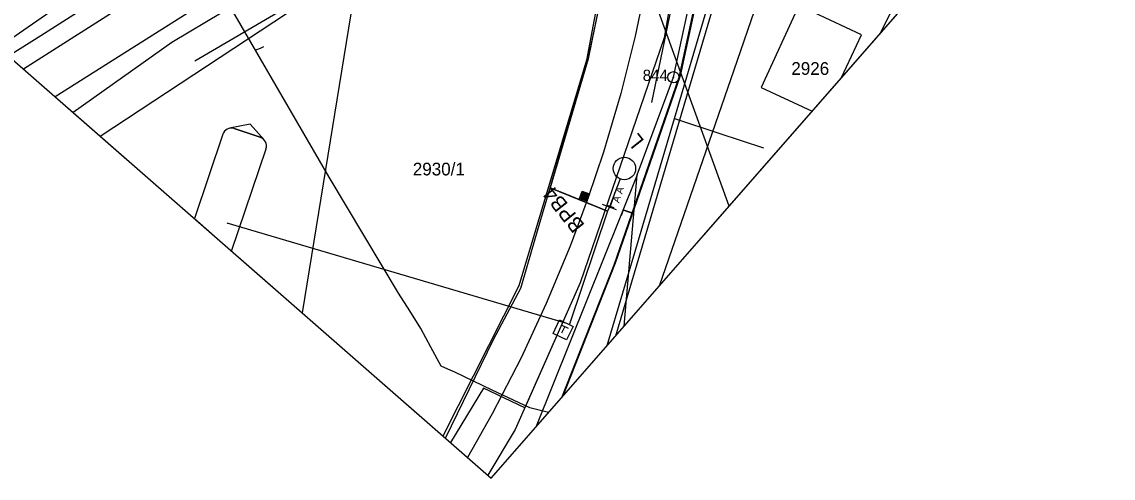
# Model space of a CAD drawing. Extents: x -620475 to -619963, y -1123010 to -1122510.
# Drawn here: x -620221.2 to -620075.4, y -1123010.1 to -1122949.2 of the extents above; entities that cross this region are included whole.
import ezdxf

# ---------------------------------------------------------------- set-up
doc = ezdxf.new("R2010")
doc.units = 0
for name, color, linetype in [('CETIN', 7, 'Continuous'), ('HranDP', 7, 'Continuous'), ('Hranice parcel', 7, 'Continuous'), ('Level 10', 7, 'Continuous'), ('lomové body trasa', 7, 'Continuous'), ('Parcelní čísla', 7, 'Continuous'), ('PS 06-14-01_trasa_sdělovací_nové', 7, 'Continuous'), ('PS6-14-01_bubliny', 7, 'Continuous'), ('Rámečky', 7, 'Continuous'), ('Rámečky-tisk', 7, 'Continuous'), ('SSZT', 7, 'Continuous'), ('SSZT-DK', 7, 'Continuous'), ('SSZT-OSS', 7, 'Continuous'), ('SSZT-TK', 7, 'Continuous'), ('VAS el kabel', 7, 'Continuous'), ('VAS vodovod', 7, 'Continuous'), ('Vnitřní kresba', 7, 'Continuous'), ('Vrstva 1', 7, 'Continuous'), ('Vrstva 2', 7, 'Continuous'), ('Vrstva 3', 7, 'Continuous'), ('Vrstva 6', 7, 'Continuous'), ('Značky bodu BP', 7, 'Continuous'), ('ČD-T', 7, 'Continuous'), ('ČD-T OSS Ždár', 7, 'Continuous')]:
    doc.layers.add(name, color=color, linetype=linetype)

# ---------------------------------------------------------------- blocks, each defined once
blk = doc.blocks.new('C535')
at = {"layer": 'Level 10'}
for p, q in [((-0.5, 0.5), (0.5, 0.5)), ((0, 0.5), (0, -0.5))]:
    blk.add_line(p, q, dxfattribs=at)
blk.add_lwpolyline([(-1, 1), (1, 1), (1, -1), (-1, -1), (-1, 1)], dxfattribs=at)

msp = doc.modelspace()

# ---------------------------------------------------------------- linework, layer by layer
at = {"layer": 'CETIN'}
for points in [[(-620222.97, -1122953.74), (-620218.63, -1122950.99), (-620187.55, -1122931.18), (-620162.84, -1122907.83)], [(-620210.74, -1122964.44), (-620141.26, -1122918.68), (-620127.25, -1122919.48)], [(-620084.31, -1122923.86), (-620095.91, -1122929.69), (-620106.59, -1122950.81)]]:
    msp.add_lwpolyline(points, dxfattribs=at)
at = {"layer": 'HranDP'}
for points in [[(-620139.01, -1122969.61), (-620134.15, -1122956.58), (-620131.17, -1122942.74), (-620127.22, -1122908.12)], [(-620139.31, -1122915.18), (-620140.08, -1122924.01), (-620145.74, -1122954.29), (-620154.8, -1122984.44), (-620164.93, -1123004.51)], [(-620139.01, -1122969.61), (-620152.54, -1123003.33)]]:
    msp.add_lwpolyline(points, dxfattribs=at)
at = {"layer": 'Hranice parcel'}
for p, q in [((-620224.32, -1122952.56), (-620208, -1122941.31)), ((-620201.16, -1122951.94), (-620214.32, -1122961.31)), ((-620140.71, -1122989.82), (-620139.01, -1122969.61))]:
    msp.add_line(p, q, dxfattribs=at)
for points in [[(-620139.01, -1122969.61), (-620134.15, -1122956.58), (-620131.17, -1122942.74), (-620127.22, -1122908.12)], [(-620139.31, -1122915.18), (-620140.08, -1122924.01), (-620145.74, -1122954.29), (-620154.8, -1122984.44), (-620164.93, -1123004.51)], [(-620175.35, -1122936.6), (-620194.44, -1122947.94), (-620201.16, -1122951.94)], [(-620175.35, -1122936.6), (-620183.73, -1122988.07)], [(-620111.68, -1122956.63), (-620109.02, -1122950.94), (-620117.41, -1122947.01), (-620122.42, -1122957.94)], [(-620122.42, -1122957.94), (-620115.6, -1122961.11)], [(-620139.01, -1122969.61), (-620152.54, -1123003.33)]]:
    msp.add_lwpolyline(points, dxfattribs=at)
at = {"layer": 'lomové body trasa'}
msp.add_line((-620142.94, -1122974.46), (-620148.04, -1122989.57), dxfattribs=at)
at = {"layer": 'PS 06-14-01_trasa_sdělovací_nové'}
for points in [[(-620158.91, -1122820.61), (-620151.64, -1122838.53), (-620148.85, -1122845.74), (-620147.08, -1122852.39), (-620142.65, -1122873.56), (-620132.31, -1122871.72), (-620130.54, -1122883.68), (-620129.88, -1122892.6), (-620129.3, -1122896.72), (-620128.92, -1122908.69), (-620129.36, -1122914.83), (-620129.69, -1122921.33), (-620138.78, -1122920.93), (-620145.54, -1122954.13), (-620150.63, -1122971.37), (-620142.94, -1122974.46), (-620142.94, -1122974.46)], [(-620164.58, -1123004.82), (-620158.18, -1122991.64), (-620154.53, -1122984.74), (-620154, -1122982.93), (-620152.3, -1122977.09), (-620150.63, -1122971.37)]]:
    msp.add_lwpolyline(points, dxfattribs=at)
at = {"layer": 'PS6-14-01_bubliny'}
for p, q in [((-620194.35, -1122964.21), (-620198.13, -1122975.47)), ((-620189.34, -1122964.61), (-620192.81, -1122963.44)), ((-620193.16, -1122979.82), (-620188.57, -1122966.15)), ((-620198.13, -1122975.47), (-620193.16, -1122979.82)), ((-620193.81, -1122976.02), (-620148.45, -1122989.44))]:
    msp.add_line(p, q, dxfattribs=at)
for points in [[(-620188.82, -1122964.95), (-620190.69, -1122962.87), (-620193.43, -1122963.4)], [(-620192.81, -1122963.44), (-620189.34, -1122964.61)]]:
    msp.add_lwpolyline(points, dxfattribs=at)
for centre, start, end in [((-620193.2, -1122964.6), 71.4447, 161.4447), ((-620193.2, -1122964.6), 71.4447, 100.9964), ((-620189.73, -1122965.76), 41.8928, 71.4447), ((-620189.73, -1122965.76), 341.4447, 71.4447)]:
    msp.add_arc(centre, 1.22, start, end, dxfattribs=at)
at = {"layer": 'Rámečky'}
msp.add_line((-620158.49, -1123010.14), (-619962.95, -1122786.6), dxfattribs=at)
for points in [[(-620279.07, -1122510.07), (-620474.61, -1122733.62), (-620158.49, -1123010.14)], [(-620126.7, -1122973.8), (-620157.19, -1122889.6), (-620255.57, -1122925.22)], [(-620255.57, -1122925.22), (-620158.49, -1123010.14), (-620126.7, -1122973.8)]]:
    msp.add_lwpolyline(points, dxfattribs=at)
at = {"layer": 'Rámečky-tisk'}
for points in [[(-620279.07, -1122510.07), (-620474.61, -1122733.62), (-620158.49, -1123010.14)], [(-620158.49, -1123010.14), (-619962.95, -1122786.6), (-620279.07, -1122510.07)], [(-620126.7, -1122973.8), (-620157.19, -1122889.6), (-620255.57, -1122925.22)], [(-620255.57, -1122925.22), (-620158.49, -1123010.14), (-620126.7, -1122973.8)]]:
    msp.add_lwpolyline(points, dxfattribs=at)
at = {"layer": 'SSZT'}
msp.add_lwpolyline([(-620139.35, -1122912.91), (-620136.81, -1122914.32), (-620131.71, -1122914.32), (-620133.48, -1122940.23), (-620135.4, -1122951.34), (-620146.6, -1122984.04), (-620154, -1123000.74), (-620159.53, -1122998.12), (-620163.93, -1123005.39)], dxfattribs=at)
at = {"layer": 'SSZT-DK'}
msp.add_lwpolyline([(-620110.3, -1122902.14), (-620109.5, -1122903.98), (-620122.01, -1122910.7), (-620123.23, -1122911.38), (-620124.41, -1122912.62), (-620125.13, -1122913.84), (-620126.05, -1122915.99), (-620127.1, -1122919.36), (-620128.15, -1122923.58), (-620130.4, -1122942.58), (-620131.92, -1122949.61), (-620133.43, -1122956.64), (-620137.1, -1122967.18), (-620142.13, -1122981.67), (-620149.09, -1122999.4)], dxfattribs=at)
at = {"layer": 'SSZT-OSS'}
msp.add_lwpolyline([(-620108.53, -1122904.71), (-620127.05, -1122914.5), (-620132.21, -1122917.23), (-620133.19, -1122941.25), (-620137.06, -1122959.97)], dxfattribs=at)
at = {"layer": 'SSZT-TK'}
msp.add_lwpolyline([(-620131.71, -1122914.32), (-620133.48, -1122940.23), (-620135.4, -1122951.34), (-620146.6, -1122984.04), (-620155.29, -1123003.62), (-620158.93, -1123009.76)], dxfattribs=at)
at = {"layer": 'VAS el kabel'}
msp.add_lwpolyline([(-620136, -1122984.43), (-620126.05, -1122955.59), (-620113.38, -1122918.86), (-620112.63, -1122916.42), (-620111.87, -1122913.98), (-620119.68, -1122904.13), (-620127.48, -1122894.28), (-620127.18, -1122894), (-620126.89, -1122893.72)], dxfattribs=at)
at = {"layer": 'VAS vodovod'}
for points in [[(-620142.98, -1122992.41), (-620138.82, -1122978.35), (-620134.02, -1122962.12), (-620127.91, -1122941.45), (-620121.79, -1122920.78), (-620120.52, -1122917.15), (-620119.24, -1122913.52), (-620115.38, -1122909), (-620111.52, -1122904.47), (-620108.12, -1122900.4), (-620104.72, -1122896.32), (-620104.31, -1122896.03), (-620103.9, -1122895.74), (-620097.91, -1122891.45), (-620091.91, -1122887.16), (-620088.52, -1122882.87), (-620085.12, -1122878.57), (-620078.3, -1122874.06), (-620071.49, -1122869.56), (-620071.48, -1122869.55), (-620060.44, -1122861.92), (-620049.39, -1122854.28), (-620049.25, -1122854.18), (-620049.11, -1122854.08)], [(-620066.7, -1122866.75), (-620084.48, -1122879.15), (-620087.92, -1122883.48), (-620091.35, -1122887.82), (-620097.77, -1122892.33), (-620104.18, -1122896.85), (-620107.54, -1122900.98), (-620110.9, -1122905.1), (-620114.72, -1122909.55), (-620118.54, -1122913.99), (-620119.85, -1122917.55), (-620121.16, -1122921.1), (-620132.06, -1122957.94), (-620141.89, -1122991.16)], [(-620163.36, -1122996), (-620164.27, -1122995.59), (-620165.18, -1122995.18), (-620166.54, -1122992.66), (-620167.89, -1122990.14), (-620169.38, -1122987.78), (-620170.86, -1122985.43), (-620175.49, -1122977.69), (-620180.12, -1122969.95), (-620186.4, -1122959.11), (-620192.67, -1122948.28), (-620196.69, -1122941.97), (-620200.71, -1122935.66), (-620201.19, -1122934.8), (-620201.57, -1122934.15), (-620201.95, -1122933.49), (-620206.59, -1122935.78), (-620211.24, -1122938.06), (-620213.31, -1122938.98), (-620215.39, -1122939.89), (-620219.47, -1122942.33), (-620223.56, -1122944.78), (-620227.81, -1122947.72), (-620228.96, -1122948.51)], [(-620189.96, -1122952.96), (-620189.87, -1122952.93), (-620189.78, -1122952.9), (-620189.33, -1122952.7), (-620188.87, -1122952.5)], [(-620134.02, -1122962.12), (-620128.07, -1122964.07), (-620122.12, -1122966.03)], [(-620150.83, -1123001.38), (-620151.89, -1123001.12), (-620153.35, -1123000.76), (-620158.35, -1122998.38), (-620163.36, -1122996)]]:
    msp.add_lwpolyline(points, dxfattribs=at)
at = {"layer": 'Vnitřní kresba'}
for p, q in [((-620144.7, -1122906.96), (-620220.97, -1122955.49)), ((-620141.9, -1122911.85), (-620216.73, -1122959.2))]:
    msp.add_line(p, q, dxfattribs=at)
at = {"layer": 'Vrstva 1'}
for p, q in [((-620148.83, -1122972.09), (-620150.63, -1122971.37)), ((-620142.94, -1122974.46), (-620148.83, -1122972.09)), ((-620142.71, -1122973.89), (-620142.94, -1122974.46))]:
    msp.add_line(p, q, dxfattribs=at)
for points in [[(-620150.63, -1122971.37), (-620145.98, -1122955.43), (-620145.54, -1122954.13), (-620141.24, -1122933.85), (-620138.78, -1122920.93), (-620138.43, -1122920.94)], [(-620137.6, -1122943.19), (-620139.25, -1122951.1), (-620141.18, -1122958.74), (-620143.49, -1122966.59), (-620145.52, -1122972.66), (-620147.96, -1122979.17), (-620151.13, -1122986.8), (-620154.5, -1122994.08), (-620158.35, -1123001.53), (-620161.67, -1123007.37)], [(-620164.58, -1123004.82), (-620158.18, -1122991.64), (-620154.53, -1122984.74), (-620154, -1122982.93), (-620152.3, -1122977.09), (-620150.63, -1122971.37)]]:
    msp.add_lwpolyline(points, dxfattribs=at)
at = {"layer": 'Vrstva 2'}
for p, q in [((-620141.25, -1122970.17), (-620142.71, -1122973.89)), ((-620146.62, -1122972.63), (-620146.51, -1122972.86)), ((-620146.56, -1122972.45), (-620146.34, -1122972.92)), ((-620146.5, -1122972.28), (-620146.16, -1122972.98)), ((-620146.44, -1122972.1), (-620145.99, -1122973.05)), ((-620146.38, -1122971.93), (-620145.81, -1122973.11)), ((-620146.28, -1122971.83), (-620145.68, -1122973.09)), ((-620146.1, -1122971.89), (-620145.61, -1122972.92)), ((-620145.93, -1122971.95), (-620145.55, -1122972.74)), ((-620145.75, -1122972.02), (-620145.49, -1122972.57)), ((-620145.58, -1122972.08), (-620145.43, -1122972.39)), ((-620145.4, -1122972.14), (-620145.37, -1122972.22)), ((-620143.65, -1122973.53), (-620141.78, -1122974.26))]:
    msp.add_line(p, q, dxfattribs=at)
msp.add_lwpolyline([(-620145.35, -1122972.16), (-620145.7, -1122973.15), (-620146.69, -1122972.8), (-620146.34, -1122971.81)], close=True, dxfattribs=at)
msp.add_lwpolyline([(-620145.35, -1122972.16), (-620145.7, -1122973.15), (-620146.69, -1122972.8), (-620146.34, -1122971.81)], close=True, dxfattribs=at)
msp.add_circle((-620140.7, -1122968.78), 1.5, dxfattribs=at)
at = {"layer": 'Vrstva 6'}
for p, q in [((-620141.96, -1122971.97), (-620142.59, -1122973.84)), ((-620143.06, -1122973.69), (-620142.12, -1122974))]:
    msp.add_line(p, q, dxfattribs=at)
at = {"layer": 'Značky bodu BP'}
for radius in [0.75, 0.03]:
    msp.add_circle((-620134.15, -1122956.58), radius, dxfattribs=at)
at = {"layer": 'ČD-T'}
msp.add_lwpolyline([(-620110.11, -1122901.9), (-620109.17, -1122904.01), (-620121.71, -1122910.62), (-620123.19, -1122911.43), (-620124.35, -1122912.67), (-620125.05, -1122913.87), (-620125.86, -1122915.76), (-620126.91, -1122919.13), (-620127.96, -1122923.34), (-620130.21, -1122942.34), (-620131.73, -1122949.38), (-620133.25, -1122956.41), (-620136.91, -1122966.94), (-620141.94, -1122981.44), (-620148.92, -1122999.2)], dxfattribs=at)
at = {"layer": 'ČD-T OSS Ždár'}
msp.add_lwpolyline([(-620090.83, -1122896.18), (-620117.32, -1122909.73), (-620123.83, -1122913.06), (-620127.58, -1122923.44), (-620145.63, -1122923.72), (-620198.1, -1122954.46)], dxfattribs=at)

# ---------------------------------------------------------------- block references
at = {"layer": 'PS 06-14-01_trasa_sdělovací_nové', "rotation": -25.43387860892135}
msp.add_blockref('C535', (-620148.89, -1122990.34), dxfattribs=at)

# ---------------------------------------------------------------- texts
at = {"layer": 'Parcelní čísla'}
for s, p in [('2926', (-620118.4, -1122956.27)), ('2930/1', (-620168.96, -1122969.7))]:
    msp.add_text(s, height=1.7, dxfattribs=at).set_placement(p)
at = {"layer": 'Vrstva 3'}
for s, p in [('L', (-620137.97, -1122965.09)), ('BPB4', (-620145.92, -1122976.33))]:
    msp.add_text(s, height=2, rotation=128.542, dxfattribs=at).set_placement(p)
at = {"layer": 'Vrstva 6'}
for s, height, rotation, p in [('  A A ', 1, 71.5027, (-620141.64, -1122974.16)), ('L', 1.5, 251.5027, (-620140.85, -1122974.05))]:
    msp.add_text(s, height=height, rotation=rotation, dxfattribs=at).set_placement(p)
at = {"layer": 'Značky bodu BP'}
msp.add_text('844', height=1.5, dxfattribs=at).set_placement((-620138.25, -1122957.08))

doc.saveas('drawing.dxf')
